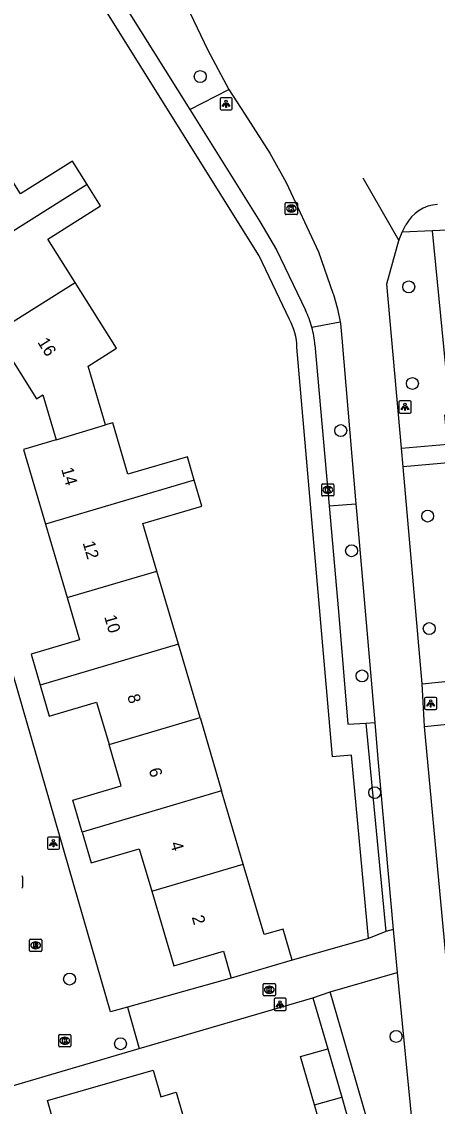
# Model space of a CAD drawing. Extents: x 158461 to 159795, y 387220 to 388672.
# Drawn here: x 159067.3 to 159101.4, y 388032.1 to 388121.2 of the extents above; entities that cross this region are included whole.
import ezdxf

# ---------------------------------------------------------------- set-up
doc = ezdxf.new("R2010")
doc.units = 0
for name, color, linetype in [('IMGEO_Boom', 7, 'Continuous'), ('IMGEO_Fietspad_gesloten', 7, 'Continuous'), ('IMGEO_Fietspad_open', 7, 'Continuous'), ('IMGEO_Groenvoorziening', 7, 'Continuous'), ('IMGEO_Kolk', 7, 'Continuous'), ('IMGEO_Lichtpunt', 7, 'Continuous'), ('IMGEO_Pand', 7, 'Continuous'), ('IMGEO_Pand_nummerreeks', 7, 'Continuous'), ('IMGEO_Rijbaan_lokaal_open', 7, 'Continuous'), ('IMGEO_Rioolput', 7, 'Continuous'), ('IMGEO_Voetpad_open', 7, 'Continuous')]:
    doc.layers.add(name, color=color, linetype=linetype)

msp = doc.modelspace()

# ---------------------------------------------------------------- linework, layer by layer
at = {"layer": 'IMGEO_Boom'}
for centre in [(159081.94, 388116.676), (159099.059, 388099.408), (159099.36, 388091.475), (159093.479, 388087.612), (159100.611, 388080.589), (159094.365, 388077.742), (159100.741, 388071.357), (159095.225, 388067.466), (159096.265, 388057.888), (159071.22, 388042.583), (159098.025, 388037.87), (159075.4, 388037.272)]:
    msp.add_circle(centre, 0.489, dxfattribs=at)
at = {"layer": 'IMGEO_Fietspad_gesloten'}
for points in [[(159075.012, 388136.993), (159077.926, 388129.094), (159079.7, 388124.896), (159082.53, 388118.898), (159084.282, 388115.609)], [(159084.282, 388115.609), (159085.6, 388113.577), (159087.655, 388110.396), (159088.996, 388107.974), (159091.643, 388102.294), (159092.837, 388098.894), (159092.875, 388098.783), (159093.217, 388097.607), (159093.425, 388096.54)], [(159095.284, 388108.356), (159098.236, 388103.215)], [(159098.462, 388086.155), (159097.268, 388099.665), (159098.236, 388103.215)], [(159093.425, 388096.54), (159093.451, 388096.404), (159093.578, 388095.186), (159094.727, 388081.583)], [(159098.598, 388084.627), (159098.462, 388086.155)], [(159100.171, 388066.828), (159098.598, 388084.627)], [(159094.727, 388081.583), (159094.803, 388080.684), (159096.277, 388063.645)], [(159100.343, 388063.322), (159100.171, 388066.828)], [(159096.277, 388063.645), (159096.535, 388060.657), (159097.792, 388046.657)], [(159103.262, 388032.237), (159100.343, 388063.322)], [(159097.792, 388046.657), (159098.11, 388043.12)], [(159098.11, 388043.12), (159099.438, 388029.434)]]:
    msp.add_lwpolyline(points, dxfattribs=at)
at = {"layer": 'IMGEO_Fietspad_open'}
for points in [[(159098.515, 388103.902), (159098.814, 388104.489)], [(159098.236, 388103.215), (159098.515, 388103.902)]]:
    msp.add_lwpolyline(points, dxfattribs=at)
msp.add_arc((159101.647, 388102.98), 3.21, 93.86371, 151.96675, dxfattribs=at)
at = {"layer": 'IMGEO_Groenvoorziening'}
for points in [[(159081.098, 388113.961), (159084.282, 388115.609)], [(159102.499, 388088.931), (159100.998, 388104.013)], [(159091.107, 388096.088), (159093.425, 388096.54)], [(159092.534, 388081.437), (159094.727, 388081.583)], [(159095.53, 388063.597), (159096.277, 388063.645)]]:
    msp.add_lwpolyline(points, dxfattribs=at)
at = {"layer": 'IMGEO_Kolk'}
for p, q in [((159088.927, 388105.411), (159088.927, 388106.263)), ((159089.002, 388106.337), (159089.854, 388106.337)), ((159089.415, 388106.117), (159089.44, 388106.117)), ((159089.928, 388106.263), (159089.928, 388105.411)), ((159089.854, 388105.337), (159089.002, 388105.337)), ((159089.438, 388105.557), (159089.413, 388105.557)), ((159091.916, 388082.314), (159091.916, 388083.166)), ((159091.991, 388083.24), (159092.843, 388083.24)), ((159092.404, 388083.02), (159092.429, 388083.02)), ((159092.917, 388083.166), (159092.917, 388082.314)), ((159092.843, 388082.24), (159091.991, 388082.24)), ((159092.427, 388082.46), (159092.402, 388082.46)), ((159067.364, 388050.967), (159067.364, 388050.115)), ((159087.117, 388041.28), (159087.117, 388042.132)), ((159087.192, 388042.206), (159088.044, 388042.206)), ((159087.605, 388041.986), (159087.63, 388041.986)), ((159088.118, 388042.132), (159088.118, 388041.28)), ((159088.044, 388041.206), (159087.192, 388041.206)), ((159087.628, 388041.426), (159087.603, 388041.426)), ((159070.325, 388037.094), (159070.325, 388037.946)), ((159070.4, 388038.02), (159071.252, 388038.02)), ((159070.813, 388037.8), (159070.838, 388037.8)), ((159071.326, 388037.946), (159071.326, 388037.094)), ((159071.252, 388037.02), (159070.4, 388037.02)), ((159070.836, 388037.24), (159070.811, 388037.24))]:
    msp.add_line(p, q, dxfattribs=at)
for points in [[(159088.927, 388105.411), (159088.927, 388106.263)], [(159089.002, 388106.337), (159089.854, 388106.337)], [(159089.248, 388106.037), (159089.371, 388106.037), (159089.371, 388105.886), (159089.501, 388106.037), (159089.665, 388106.037), (159089.519, 388105.886), (159089.672, 388105.637), (159089.52, 388105.637), (159089.435, 388105.801), (159089.371, 388105.734), (159089.371, 388105.637), (159089.248, 388105.637), (159089.248, 388106.037)], [(159089.928, 388106.263), (159089.928, 388105.411)], [(159089.854, 388105.337), (159089.002, 388105.337)], [(159091.916, 388082.314), (159091.916, 388083.166)], [(159091.991, 388083.24), (159092.843, 388083.24)], [(159092.237, 388082.94), (159092.36, 388082.94), (159092.36, 388082.789), (159092.49, 388082.94), (159092.654, 388082.94), (159092.508, 388082.789), (159092.661, 388082.54), (159092.509, 388082.54), (159092.424, 388082.704), (159092.36, 388082.637), (159092.36, 388082.54), (159092.237, 388082.54), (159092.237, 388082.94)], [(159092.917, 388083.166), (159092.917, 388082.314)], [(159092.843, 388082.24), (159091.991, 388082.24)], [(159067.364, 388050.967), (159067.364, 388050.115)], [(159087.117, 388041.28), (159087.117, 388042.132)], [(159087.192, 388042.206), (159088.044, 388042.206)], [(159087.438, 388041.906), (159087.561, 388041.906), (159087.561, 388041.755), (159087.691, 388041.906), (159087.855, 388041.906), (159087.709, 388041.755), (159087.862, 388041.506), (159087.71, 388041.506), (159087.625, 388041.67), (159087.561, 388041.603), (159087.561, 388041.506), (159087.438, 388041.506), (159087.438, 388041.906)], [(159088.118, 388042.132), (159088.118, 388041.28)], [(159088.044, 388041.206), (159087.192, 388041.206)], [(159070.325, 388037.094), (159070.325, 388037.946)], [(159070.4, 388038.02), (159071.252, 388038.02)], [(159070.646, 388037.72), (159070.769, 388037.72), (159070.769, 388037.569), (159070.899, 388037.72), (159071.063, 388037.72), (159070.917, 388037.569), (159071.07, 388037.32), (159070.918, 388037.32), (159070.833, 388037.484), (159070.769, 388037.417), (159070.769, 388037.32), (159070.646, 388037.32), (159070.646, 388037.72)], [(159071.326, 388037.946), (159071.326, 388037.094)], [(159071.252, 388037.02), (159070.4, 388037.02)]]:
    msp.add_lwpolyline(points, dxfattribs=at)
for centre, start, end in [((159089.004, 388106.261), 91.55205, 178.44795), ((159089.004, 388106.261), 91.55205, 178.44795), ((159089.852, 388106.261), 1.55205, 88.44795), ((159089.852, 388106.261), 1.55205, 88.44795), ((159089.004, 388105.413), 181.55205, 268.44795), ((159089.004, 388105.413), 181.55205, 268.44795), ((159089.852, 388105.413), 271.55205, 358.44795), ((159089.852, 388105.413), 271.55205, 358.44795), ((159091.993, 388083.164), 91.55205, 178.44795), ((159091.993, 388083.164), 91.55205, 178.44795), ((159092.841, 388083.164), 1.55205, 88.44795), ((159092.841, 388083.164), 1.55205, 88.44795), ((159091.993, 388082.316), 181.55205, 268.44795), ((159091.993, 388082.316), 181.55205, 268.44795), ((159092.841, 388082.316), 271.55205, 358.44795), ((159092.841, 388082.316), 271.55205, 358.44795), ((159067.288, 388050.965), 1.55205, 88.44795), ((159067.288, 388050.965), 1.55205, 88.44795), ((159067.288, 388050.117), 271.55205, 358.44795), ((159067.288, 388050.117), 271.55205, 358.44795), ((159087.194, 388042.13), 91.55205, 178.44795), ((159087.194, 388042.13), 91.55205, 178.44795), ((159088.042, 388042.13), 1.55205, 88.44795), ((159088.042, 388042.13), 1.55205, 88.44795), ((159087.194, 388041.282), 181.55205, 268.44795), ((159087.194, 388041.282), 181.55205, 268.44795), ((159088.042, 388041.282), 271.55205, 358.44795), ((159088.042, 388041.282), 271.55205, 358.44795), ((159070.402, 388037.944), 91.55205, 178.44795), ((159070.402, 388037.944), 91.55205, 178.44795), ((159071.25, 388037.944), 1.55205, 88.44795), ((159071.25, 388037.944), 1.55205, 88.44795), ((159070.402, 388037.096), 181.55205, 268.44795), ((159070.402, 388037.096), 181.55205, 268.44795), ((159071.25, 388037.096), 271.55205, 358.44795), ((159071.25, 388037.096), 271.55205, 358.44795)]:
    msp.add_arc(centre, 0.0765, start, end, dxfattribs=at)
for centre, major_axis, ratio, start_param, end_param in [((159089.414, 388105.837), (-0.387, 0.002), 0.722429, 4.712389, 7.853982), ((159089.439, 388105.837), (-0.39, 0.002), 0.717154, 1.570796, 4.712389), ((159092.403, 388082.74), (-0.387, 0.002), 0.722429, 4.712389, 7.853982), ((159092.428, 388082.74), (-0.39, 0.002), 0.717154, 1.570796, 4.712389), ((159087.604, 388041.706), (-0.387, 0.002), 0.722429, 4.712389, 7.853982), ((159087.629, 388041.706), (-0.39, 0.002), 0.717154, 1.570796, 4.712389), ((159070.812, 388037.52), (-0.387, 0.002), 0.722429, 4.712389, 7.853982), ((159070.837, 388037.52), (-0.39, 0.002), 0.717154, 1.570796, 4.712389)]:
    msp.add_ellipse(centre, major_axis=major_axis, ratio=ratio, start_param=start_param, end_param=end_param, dxfattribs=at)
at = {"layer": 'IMGEO_Lichtpunt'}
for p, q in [((159083.569, 388114.837), (159083.569, 388114.03)), ((159083.569, 388114.837), (159083.569, 388114.03)), ((159084.471, 388114.932), (159083.663, 388114.932)), ((159084.471, 388114.932), (159083.663, 388114.932)), ((159084.565, 388114.03), (159084.565, 388114.837)), ((159084.565, 388114.03), (159084.565, 388114.837)), ((159083.663, 388113.936), (159084.471, 388113.936)), ((159083.663, 388113.936), (159084.471, 388113.936)), ((159098.251, 388089.952), (159098.251, 388089.145)), ((159098.251, 388089.952), (159098.251, 388089.145)), ((159099.153, 388090.047), (159098.345, 388090.047)), ((159099.153, 388090.047), (159098.345, 388090.047)), ((159099.247, 388089.145), (159099.247, 388089.952)), ((159099.247, 388089.145), (159099.247, 388089.952)), ((159098.345, 388089.051), (159099.153, 388089.051)), ((159098.345, 388089.051), (159099.153, 388089.051)), ((159100.359, 388065.616), (159100.359, 388064.809)), ((159100.359, 388065.616), (159100.359, 388064.809)), ((159101.261, 388065.711), (159100.453, 388065.711)), ((159101.261, 388065.711), (159100.453, 388065.711)), ((159101.355, 388064.809), (159101.355, 388065.616)), ((159101.355, 388064.809), (159101.355, 388065.616)), ((159100.453, 388064.715), (159101.261, 388064.715)), ((159100.453, 388064.715), (159101.261, 388064.715)), ((159069.397, 388054.141), (159069.397, 388053.334)), ((159069.397, 388054.141), (159069.397, 388053.334)), ((159070.299, 388054.236), (159069.491, 388054.236)), ((159070.299, 388054.236), (159069.491, 388054.236)), ((159070.393, 388053.334), (159070.393, 388054.141)), ((159070.393, 388053.334), (159070.393, 388054.141)), ((159069.491, 388053.24), (159070.299, 388053.24)), ((159069.491, 388053.24), (159070.299, 388053.24)), ((159088.902, 388041.002), (159088.094, 388041.002)), ((159088.902, 388041.002), (159088.094, 388041.002)), ((159088, 388040.907), (159088, 388040.1)), ((159088, 388040.907), (159088, 388040.1)), ((159088.996, 388040.1), (159088.996, 388040.907)), ((159088.996, 388040.1), (159088.996, 388040.907)), ((159088.094, 388040.006), (159088.902, 388040.006)), ((159088.094, 388040.006), (159088.902, 388040.006))]:
    msp.add_line(p, q, dxfattribs=at)
for points in [[(159083.943, 388114.501), (159083.982, 388114.473), (159083.794, 388114.211), (159083.756, 388114.238), (159083.943, 388114.501)], [(159084.045, 388114.453), (159084.092, 388114.453), (159084.092, 388114.131), (159084.045, 388114.131), (159084.045, 388114.453)], [(159084.155, 388114.473), (159084.193, 388114.5), (159084.38, 388114.238), (159084.341, 388114.21), (159084.155, 388114.473)], [(159098.625, 388089.616), (159098.664, 388089.588), (159098.476, 388089.326), (159098.438, 388089.353), (159098.625, 388089.616)], [(159098.727, 388089.568), (159098.774, 388089.568), (159098.774, 388089.246), (159098.727, 388089.246), (159098.727, 388089.568)], [(159098.837, 388089.588), (159098.875, 388089.615), (159099.062, 388089.353), (159099.023, 388089.325), (159098.837, 388089.588)], [(159100.733, 388065.28), (159100.772, 388065.252), (159100.584, 388064.99), (159100.546, 388065.017), (159100.733, 388065.28)], [(159100.835, 388065.232), (159100.882, 388065.232), (159100.882, 388064.91), (159100.835, 388064.91), (159100.835, 388065.232)], [(159100.945, 388065.252), (159100.983, 388065.279), (159101.17, 388065.017), (159101.131, 388064.989), (159100.945, 388065.252)], [(159069.771, 388053.805), (159069.81, 388053.777), (159069.622, 388053.515), (159069.584, 388053.542), (159069.771, 388053.805)], [(159069.873, 388053.757), (159069.92, 388053.757), (159069.92, 388053.435), (159069.873, 388053.435), (159069.873, 388053.757)], [(159069.983, 388053.777), (159070.021, 388053.804), (159070.208, 388053.542), (159070.169, 388053.514), (159069.983, 388053.777)], [(159088.374, 388040.571), (159088.413, 388040.543), (159088.225, 388040.281), (159088.187, 388040.308), (159088.374, 388040.571)], [(159088.476, 388040.523), (159088.523, 388040.523), (159088.523, 388040.201), (159088.476, 388040.201), (159088.476, 388040.523)], [(159088.586, 388040.543), (159088.624, 388040.57), (159088.811, 388040.308), (159088.772, 388040.28), (159088.586, 388040.543)]]:
    msp.add_lwpolyline(points, dxfattribs=at)
for centre in [(159084.068, 388114.635), (159098.75, 388089.75), (159100.858, 388065.414), (159069.896, 388053.939), (159088.499, 388040.705)]:
    msp.add_circle(centre, 0.0994, dxfattribs=at)
for centre, start, end in [((159083.663, 388114.837), 90, 180), ((159083.663, 388114.837), 90, 180), ((159084.471, 388114.837), 0, 90), ((159084.471, 388114.837), 0, 90), ((159083.663, 388114.03), 180, 270), ((159083.663, 388114.03), 180, 270), ((159084.471, 388114.03), 270, 0), ((159084.471, 388114.03), 270, 360), ((159098.345, 388089.952), 90, 180), ((159098.345, 388089.952), 90, 180), ((159099.153, 388089.952), 0, 90), ((159099.153, 388089.952), 0, 90), ((159098.345, 388089.145), 180, 270), ((159098.345, 388089.145), 180, 270), ((159099.153, 388089.145), 270, 0), ((159099.153, 388089.145), 270, 360), ((159100.453, 388065.616), 90, 180), ((159100.453, 388065.616), 90, 180), ((159101.261, 388065.616), 0, 90), ((159101.261, 388065.616), 0, 90), ((159100.453, 388064.809), 180, 270), ((159100.453, 388064.809), 180, 270), ((159101.261, 388064.809), 270, 0), ((159101.261, 388064.809), 270, 360), ((159069.491, 388054.141), 90, 180), ((159069.491, 388054.141), 90, 180), ((159070.299, 388054.141), 0, 90), ((159070.299, 388054.141), 0, 90), ((159069.491, 388053.334), 180, 270), ((159069.491, 388053.334), 180, 270), ((159070.299, 388053.334), 270, 0), ((159070.299, 388053.334), 270, 360), ((159088.094, 388040.907), 90, 180), ((159088.094, 388040.907), 90, 180), ((159088.902, 388040.907), 0, 90), ((159088.902, 388040.907), 0, 90), ((159088.094, 388040.1), 180, 270), ((159088.094, 388040.1), 180, 270), ((159088.902, 388040.1), 270, 0), ((159088.902, 388040.1), 270, 360)]:
    msp.add_arc(centre, 0.0946, start, end, dxfattribs=at)
at = {"layer": 'IMGEO_Pand'}
for points in [[(159072.665, 388107.802), (159071.454, 388109.726), (159067.192, 388107.043), (159065.063, 388110.423)], [(159072.665, 388107.802), (159061.753, 388100.933)], [(159071.67, 388099.771), (159069.435, 388103.32), (159073.769, 388106.05), (159072.665, 388107.802)], [(159065.093, 388095.63), (159071.67, 388099.771)], [(159074.166, 388088.074), (159072.745, 388092.898), (159075.074, 388094.365), (159071.67, 388099.771)], [(159065.093, 388095.63), (159068.496, 388090.225), (159069.023, 388090.556), (159070.113, 388086.853)], [(159081.46, 388083.531), (159080.889, 388085.468), (159076.006, 388084.029), (159074.763, 388088.25), (159074.166, 388088.074)], [(159070.113, 388086.853), (159074.166, 388088.074)], [(159070.113, 388086.853), (159067.427, 388086.062), (159069.235, 388079.928)], [(159081.46, 388083.531), (159069.235, 388079.928)], [(159078.383, 388076.082), (159077.237, 388079.972), (159082.088, 388081.402), (159081.46, 388083.531)], [(159069.235, 388079.928), (159071.009, 388073.908)], [(159071.009, 388073.908), (159078.383, 388076.082)], [(159080.157, 388070.063), (159078.383, 388076.082)], [(159071.009, 388073.908), (159072.036, 388070.422), (159068.06, 388069.25), (159068.806, 388066.719)], [(159080.157, 388070.063), (159068.806, 388066.719)], [(159081.93, 388064.046), (159080.157, 388070.063)], [(159068.806, 388066.719), (159069.555, 388064.175), (159073.433, 388065.317), (159074.457, 388061.843)], [(159074.457, 388061.843), (159081.93, 388064.046)], [(159081.93, 388064.046), (159083.703, 388058.027)], [(159072.255, 388054.654), (159071.486, 388057.262), (159075.462, 388058.434), (159074.457, 388061.843)], [(159083.703, 388058.027), (159072.255, 388054.654)], [(159085.477, 388052.008), (159083.703, 388058.027)], [(159072.255, 388054.654), (159073.002, 388052.12), (159076.945, 388053.282), (159077.972, 388049.797)], [(159077.972, 388049.797), (159085.477, 388052.008)], [(159089.502, 388044.138), (159088.75, 388046.69), (159087.18, 388046.227), (159085.477, 388052.008)], [(159077.972, 388049.797), (159079.779, 388043.664), (159083.848, 388044.862), (159084.496, 388042.662)], [(159089.502, 388044.138), (159084.496, 388042.662)], [(159091.316, 388032.246), (159090.186, 388036.212), (159092.431, 388036.851)], [(159092.431, 388036.851), (159093.559, 388032.89)], [(159072.363, 388026.799), (159071.757, 388028.911), (159070.559, 388028.567), (159069.402, 388032.599), (159078.086, 388035.091), (159078.707, 388032.927), (159079.97, 388033.29), (159081.111, 388029.313)], [(159091.316, 388032.246), (159093.559, 388032.89)], [(159094.637, 388029.107), (159092.392, 388028.468), (159091.316, 388032.246)], [(159093.559, 388032.89), (159094.637, 388029.107)]]:
    msp.add_lwpolyline(points, dxfattribs=at)
at = {"layer": 'IMGEO_Rijbaan_lokaal_open'}
for points in [[(159075.986, 388040.282), (159074.579, 388039.888), (159061.641, 388084.638)], [(159075.986, 388040.282), (159076.928, 388036.874)], [(159066.145, 388033.716), (159076.928, 388036.874)]]:
    msp.add_lwpolyline(points, dxfattribs=at)
at = {"layer": 'IMGEO_Rioolput'}
for p, q in [((159067.933, 388044.927), (159067.933, 388045.779)), ((159068.008, 388045.853), (159068.86, 388045.853)), ((159068.421, 388045.633), (159068.446, 388045.633)), ((159068.934, 388045.779), (159068.934, 388044.927)), ((159068.86, 388044.853), (159068.008, 388044.853)), ((159068.444, 388045.073), (159068.419, 388045.073))]:
    msp.add_line(p, q, dxfattribs=at)
for points in [[(159067.933, 388044.927), (159067.933, 388045.779)], [(159068.008, 388045.853), (159068.86, 388045.853)], [(159068.522, 388045.551), (159068.27, 388045.553), (159068.27, 388045.153)], [(159068.448, 388045.472), (159068.394, 388045.472), (159068.394, 388045.391)], [(159068.394, 388045.391), (159068.446, 388045.391)], [(159068.934, 388045.779), (159068.934, 388044.927)], [(159068.86, 388044.853), (159068.008, 388044.853)], [(159068.27, 388045.153), (159068.394, 388045.153), (159068.394, 388045.315), (159068.405, 388045.315)], [(159068.452, 388045.286), (159068.523, 388045.153), (159068.663, 388045.153), (159068.598, 388045.279)]]:
    msp.add_lwpolyline(points, dxfattribs=at)
for centre, radius, start, end in [((159068.01, 388045.777), 0.0765, 91.55205, 178.44795), ((159068.01, 388045.777), 0.0765, 91.55205, 178.44795), ((159068.43, 388045.58), 0.19, 274.7715, 282.96867), ((159068.454, 388045.376), 0.0964, 77.00612, 93.18647), ((159068.468, 388045.433), 0.0378, 276.66336, 79.67722), ((159068.521, 388045.441), 0.109, 350.36119, 89.41601), ((159068.519, 388045.441), 0.112, 277.58423, 350.98172), ((159068.858, 388045.777), 0.0765, 1.55205, 88.44795), ((159068.858, 388045.777), 0.0765, 1.55205, 88.44795), ((159068.01, 388044.929), 0.0765, 181.55205, 268.44795), ((159068.01, 388044.929), 0.0765, 181.55205, 268.44795), ((159068.404, 388045.262), 0.0533, 26.02933, 88.69889), ((159068.503, 388045.226), 0.108, 29.51342, 73.79051), ((159068.858, 388044.929), 0.0765, 271.55205, 358.44795), ((159068.858, 388044.929), 0.0765, 271.55205, 358.44795)]:
    msp.add_arc(centre, radius, start, end, dxfattribs=at)
for centre, major_axis, ratio, start_param, end_param in [((159068.42, 388045.353), (-0.387, 0.002), 0.722429, 4.712389, 7.853982), ((159068.445, 388045.353), (-0.39, 0.002), 0.717154, 1.570796, 4.712389)]:
    msp.add_ellipse(centre, major_axis=major_axis, ratio=ratio, start_param=start_param, end_param=end_param, dxfattribs=at)
at = {"layer": 'IMGEO_Voetpad_open'}
for points in [[(159068.952, 388133.382), (159081.098, 388113.961)], [(159089.258, 388096.72), (159086.777, 388101.95), (159067.701, 388132.494)], [(159081.098, 388113.961), (159086.841, 388104.777), (159088.217, 388102.457), (159089.572, 388099.607), (159090.588, 388097.485)], [(159125.122, 388105.095), (159100.998, 388104.013)], [(159100.998, 388104.013), (159098.515, 388103.902)], [(159095.755, 388045.901), (159094.357, 388060.97), (159092.807, 388060.834), (159089.885, 388094.451)], [(159091.363, 388094.656), (159092.534, 388081.437)], [(159098.462, 388086.155), (159102.234, 388086.506), (159102.012, 388088.896), (159102.499, 388088.931)], [(159102.916, 388085.007), (159098.598, 388084.627)], [(159092.534, 388081.437), (159093.303, 388072.753), (159094.07, 388063.5), (159095.53, 388063.597)], [(159100.171, 388066.828), (159104.708, 388067.272)], [(159095.53, 388063.597), (159097.185, 388046.488)], [(159100.343, 388063.322), (159103.037, 388063.591)], [(159097.185, 388046.488), (159095.755, 388045.901)], [(159097.792, 388046.657), (159097.185, 388046.488)], [(159095.755, 388045.901), (159089.502, 388044.138)], [(159092.611, 388041.539), (159098.11, 388043.12)], [(159084.496, 388042.662), (159075.986, 388040.282)], [(159076.928, 388036.874), (159091.191, 388041.052)], [(159091.191, 388041.052), (159092.611, 388041.539)], [(159091.191, 388041.052), (159092.431, 388036.851)], [(159096.218, 388029.047), (159092.611, 388041.539)]]:
    msp.add_lwpolyline(points, dxfattribs=at)
for centre, radius, start, end in [((159083.102, 388093.909), 8.296, 15.22719, 25.53392), ((159085.028, 388094.33), 4.859, 1.42849, 29.466), ((159083.003, 388093.9), 8.394, 5.1648, 15.1067)]:
    msp.add_arc(centre, radius, start, end, dxfattribs=at)

# ---------------------------------------------------------------- texts
at = {"layer": 'IMGEO_Pand_nummerreeks'}
for s, rotation, p in [('16', 302.19829, (159068.554, 388094.862)), ('14', 286.24266, (159070.524, 388084.444)), ('12', 286.24266, (159072.287, 388078.39)), ('10', 286.24266, (159074.054, 388072.327)), ('8', 286.24266, (159075.947, 388065.828)), ('6', 286.24266, (159077.71, 388059.775)), ('4', 286.24266, (159079.474, 388053.718)), ('2', 286.24266, (159081.239, 388047.664))]:
    msp.add_text(s, height=1, rotation=rotation, dxfattribs=at).set_placement(p)

doc.saveas('drawing.dxf')
